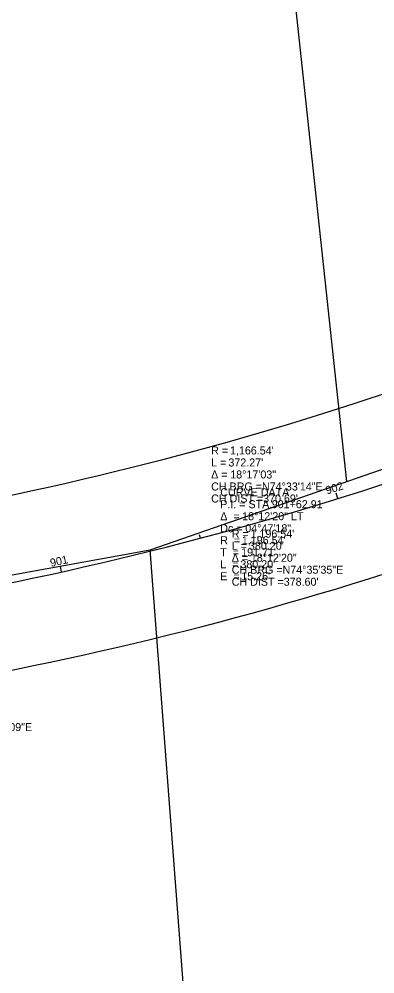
# Model space of a CAD drawing. Extents: x 2379325 to 2382869, y 256594 to 258871.
# Drawn here: x 2382312.6 to 2382437, y 257773.3 to 258107.4 of the extents above; entities that cross this region are included whole.
import ezdxf

# ---------------------------------------------------------------- set-up
doc = ezdxf.new("R2010")
doc.units = 0
for name, color, linetype in [('Default', 7, 'Continuous'), ('DR_P_GenericNode', 7, 'Continuous'), ('DR_P_Headwall', 7, 'Continuous'), ('DR_X_Culvert', 7, 'Continuous'), ('DR_X_Culvert3D', 7, 'Continuous'), ('DR_X_Storm_Sewer', 7, 'Continuous'), ('SC_Scratch2', 7, 'Continuous')]:
    doc.layers.add(name, color=color, linetype=linetype)

msp = doc.modelspace()

# ---------------------------------------------------------------- linework, layer by layer
at = {"layer": 'DR_P_GenericNode'}
msp.add_arc((2382069.07, 259082.23), 1196.54, 276.30412, 294.50972, dxfattribs=at)
at = {"layer": 'DR_P_Headwall'}
for radius, end in [(1166.54, 294.58836), (1226.54, 294.43398)]:
    msp.add_arc((2382069.07, 259082.23), radius, 276.30412, end, dxfattribs=at)
at = {"layer": 'DR_X_Culvert3D'}
for p, q in [((2382424.1, 257939.57), (2382423.5, 257941.48)), ((2382376.05, 257925.74), (2382375.74, 257926.9)), ((2382327.47, 257913.92), (2382327.04, 257915.88))]:
    msp.add_line(p, q, dxfattribs=at)
at = {"layer": 'DR_X_Storm_Sewer'}
for p, q in [((2382427.24, 257945.54), (2382408.52, 258119.54)), ((2382358.38, 257921.64), (2382613.47, 258010.17)), ((2382200.46, 257892.92), (2382358.38, 257921.64)), ((2382380.71, 257630.58), (2382358.38, 257921.64))]:
    msp.add_line(p, q, dxfattribs=at)
at = {"layer": 'SC_Scratch2'}
msp.add_arc((2382069.07, 259082.23), 1196.54, 276.30412, 294.50972, dxfattribs=at)

# ---------------------------------------------------------------- texts
at = {"layer": 'Default'}
for s, p in [('R = ', (2382379.76, 257955.02)), ("1,166.54'", (2382386.35, 257955.02)), ('L = ', (2382379.76, 257950.82)), ("372.27'", (2382385.8, 257950.82)), ('Δ = ', (2382379.76, 257946.62)), ('18°17\'03"', (2382386.44, 257946.62)), ('CH BRG = ', (2382379.76, 257942.42)), ('N74°33\'14"E', (2382397.54, 257942.42)), ('CH DIST = ', (2382379.76, 257938.22)), ("370.69'", (2382397.94, 257938.22)), ('R = ', (2382386.96, 257925.89)), ("1,196.54'", (2382393.54, 257925.89)), ('L = ', (2382386.96, 257921.69)), ("380.20'", (2382393, 257921.69)), ('Δ = ', (2382386.96, 257917.49)), ('18°12\'20"', (2382393.64, 257917.49)), ('CH BRG = ', (2382386.96, 257913.29)), ('N74°35\'35"E', (2382404.74, 257913.29)), ('CH DIST = ', (2382386.96, 257909.09)), ("378.60'", (2382405.14, 257909.09)), ('N80°11\'09"E', (2382295.92, 257858.24))]:
    msp.add_text(s, height=2.8, dxfattribs=at).set_placement(p)
at = {"layer": 'DR_X_Culvert'}
for s, p in [('CURVE DATA', (2382382.95, 257940.42)), ('P.I. = STA. ', (2382382.95, 257936.22)), ('901+62.91', (2382400.95, 257936.22)), ('Δ  = ', (2382382.95, 257932.02)), ('18°12\'20" LT', (2382390.6, 257932.02)), ('Dc = ', (2382382.95, 257927.82)), ('04°47\'18"', (2382391.7, 257927.82)), ('R  = ', (2382382.95, 257923.62)), ("1,196.54'", (2382390.49, 257923.62)), ('T  = ', (2382382.95, 257919.42)), ("191.71'", (2382390.27, 257919.42)), ('L  = ', (2382382.95, 257915.22)), ("380.20'", (2382389.99, 257915.22)), ('E  = ', (2382382.95, 257911.02)), ("15.26'", (2382390.3, 257911.02))]:
    msp.add_text(s, height=2.8, dxfattribs=at).set_placement(p)
at = {"layer": 'DR_X_Culvert3D'}
for s, rotation, p in [('902', 17.2601, (2382420.29, 257941.01)), ('901', 12.4717, (2382323.78, 257915.67))]:
    msp.add_text(s, height=2.8, rotation=rotation, dxfattribs=at).set_placement(p)

doc.saveas('drawing.dxf')
